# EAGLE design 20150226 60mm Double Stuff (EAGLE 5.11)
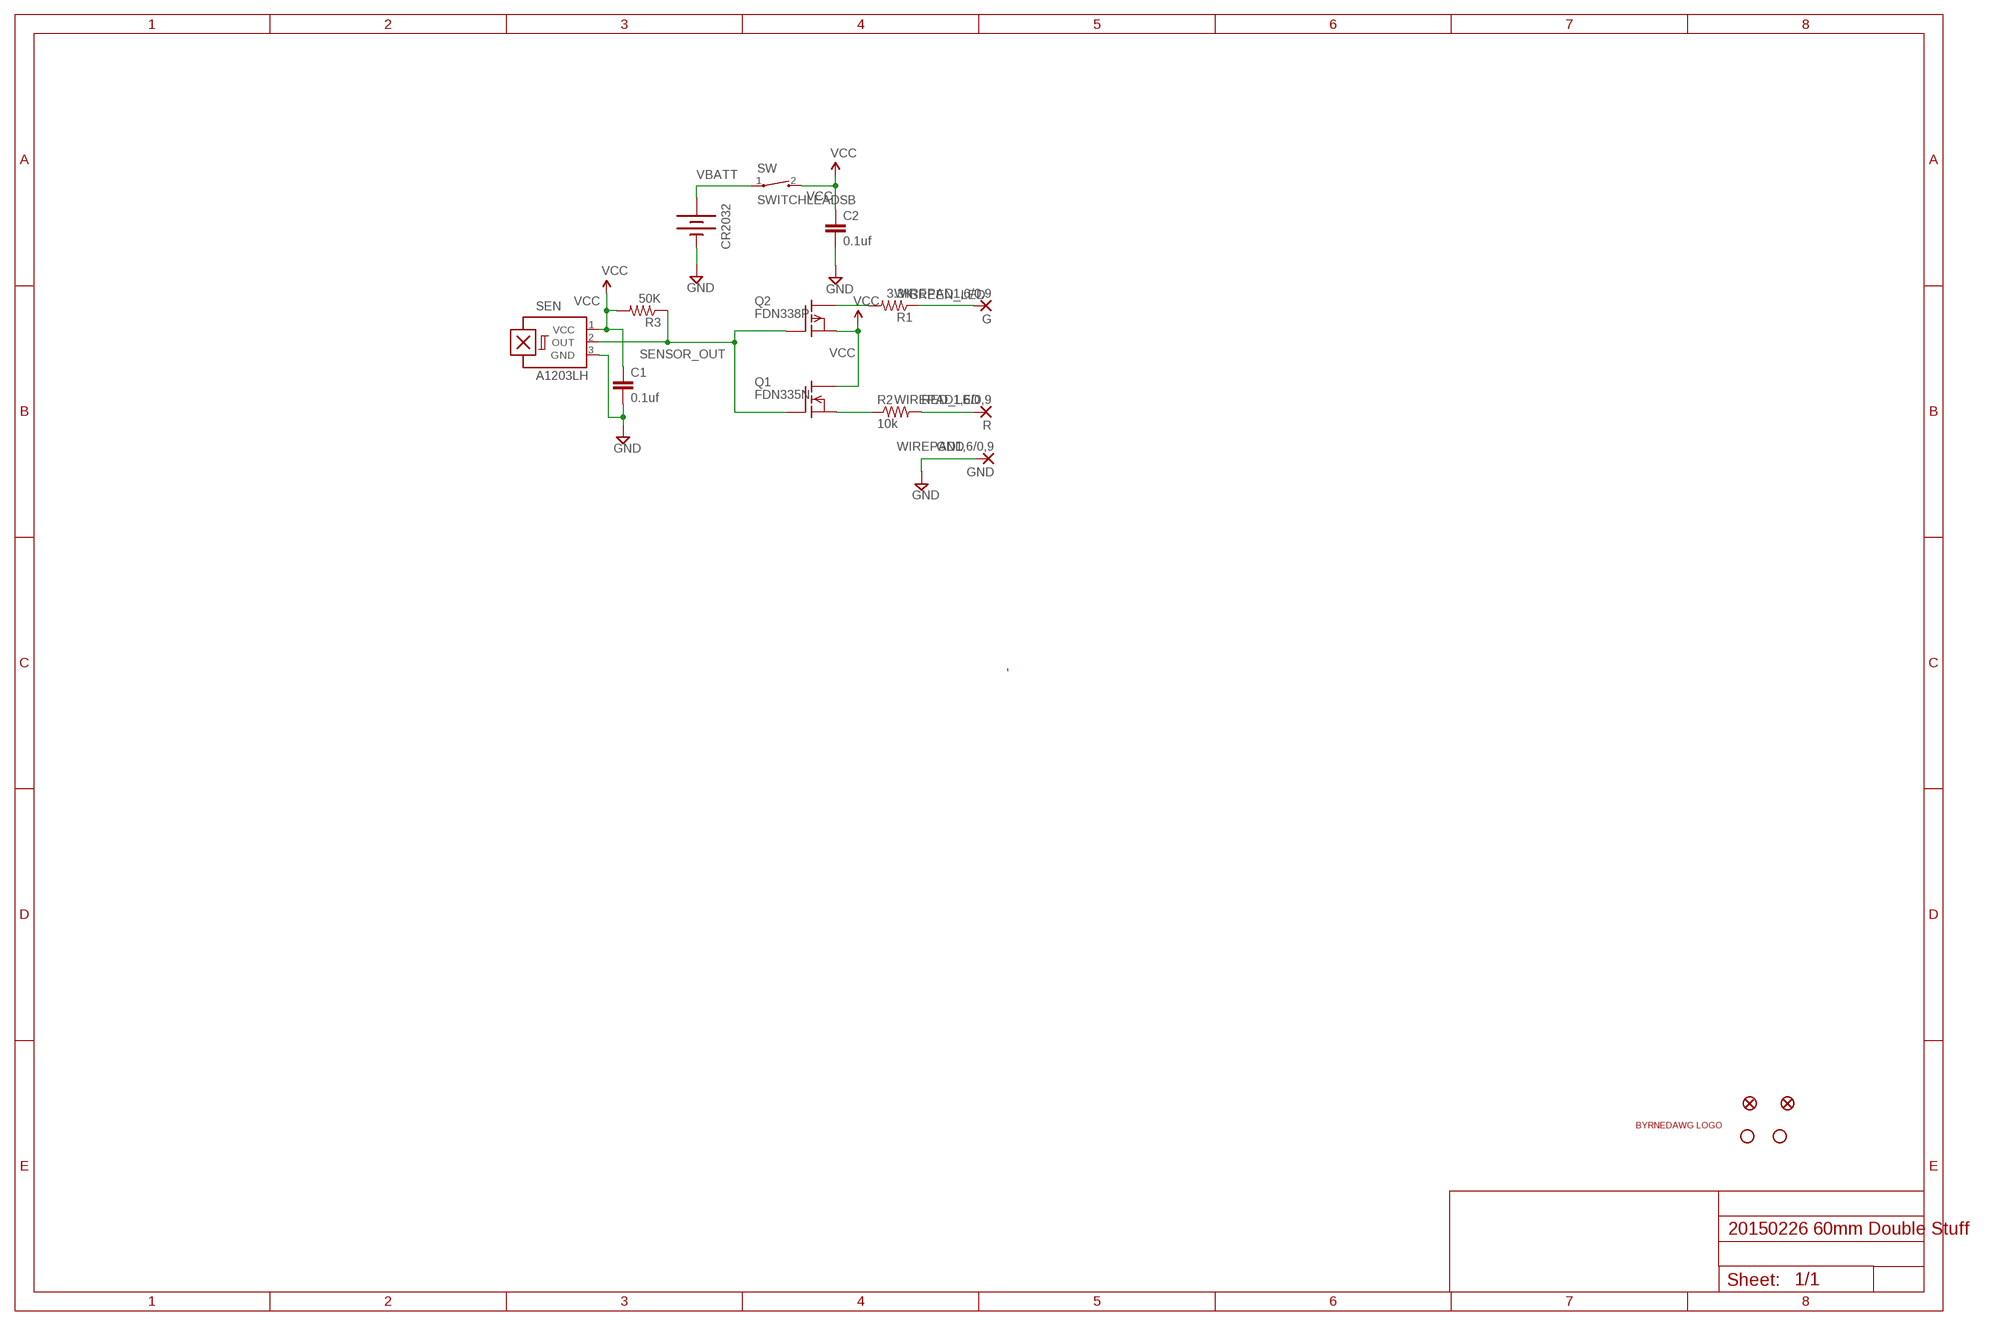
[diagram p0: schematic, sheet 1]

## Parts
C1  0.1uf  CAP0805  [0805]
C2  0.1uf  CAP0805  [0805]
CR2032  BATTERYFOB  [BATTERY_20MM_PTH_COMPACT]
G  WIREPAD1,6/0,9  [1,6/0,9]
GND  WIREPAD1,6/0,9  [1,6/0,9]
JP2  FIDUCIAL1X2  [FIDUCIAL-1X2]
JP3  FIDUCIAL1X2  [FIDUCIAL-1X2]
JP6  STAND-OFF  [STAND-OFF]
JP7  STAND-OFF  [STAND-OFF]
Q1  FDN335N  [SOT23]
Q2  FDN338P  [SOT23]
R  WIREPAD1,6/0,9  [1,6/0,9]
R1  3.3K  RESISTOR0805-RES  [0805]
R2  10k  RESISTOR0805-RES  [0805]
R3  50K  RESISTOR0805-RES  [0805]
SEN  A1203LH  [SOT23-W]
SW  SWITCHLEADSB  [1,6/0,8SWITCH]
U$2  BYRNEDAWGBIG_LABEL  [BYRNEDAWGBIGLABEL]

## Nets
GND: C1.2 C2.2 CR2032.2(-) GND.1(P) SEN.3(GND)
GREEN_LED: G.1(P) R1.1
N$1: Q1.2(S) R2.1
N$3: Q2.3(D) R1.2
RED_LED: R2.2 R.1(P)
SENSOR_OUT: Q1.1(G) Q2.1(G) R3.1 SEN.2(OUT)
VBATT: CR2032.1(+) SW.1
VCC: C1.1 C2.1 Q1.3(D) Q2.2(S) R3.2 SEN.1(VCC) SW.2

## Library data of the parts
C1 C2 = SparkFun:CAP: Capacitor
CR2032 = SparkFun:BATTERY: Battery Holders
G GND R = wirepad:WIREPAD: Wire PAD connect wire on PCB
JP2 JP3 = SparkFun:FIDUCIAL: Fiducial Alignment Points
JP6 JP7 = SparkFun:STAND-OFF: Stand Off
Q1 = fairchild-semic:FDN335N: N-Channel Enhancement MOSFET 2.5V
Q2 = fairchild-semic:FDN338P: P-Channel Enhancement MOSFET 2.5V
R1-R3 = SparkFun:RESISTOR: Resistor
SEN = allegro:A12*?: Hall-effect bipolar switch Source: http://www.allegromicro.com/en/Products/Part_Numbers/1202/1202.pdf; MF: ALLEGRO MICROSYSTEMS, INC.; MPN: A1203LLHLT-T; OC_FARNELL: 1791384; OC_NEWARK: 31K6608
SW = User_Created:SWITCHLEADS: CT10 Series Molded Switch
U$2 = logo:BYRNEDAWG

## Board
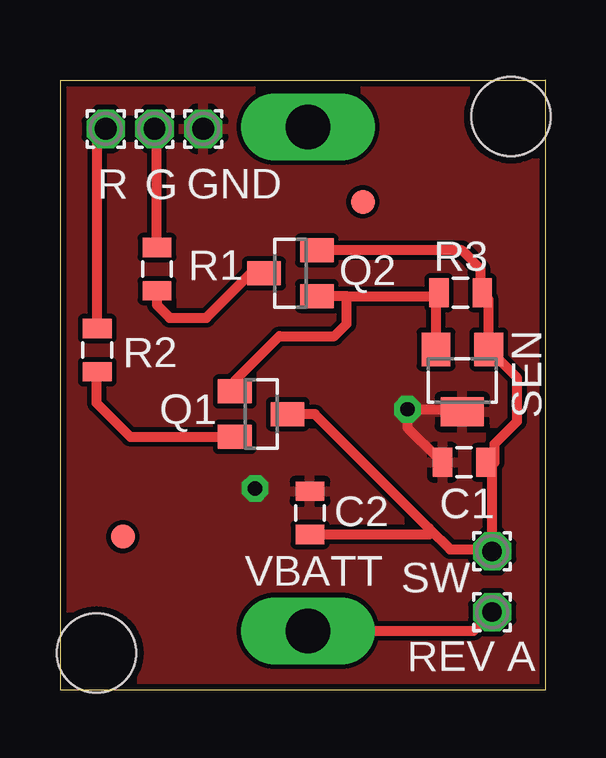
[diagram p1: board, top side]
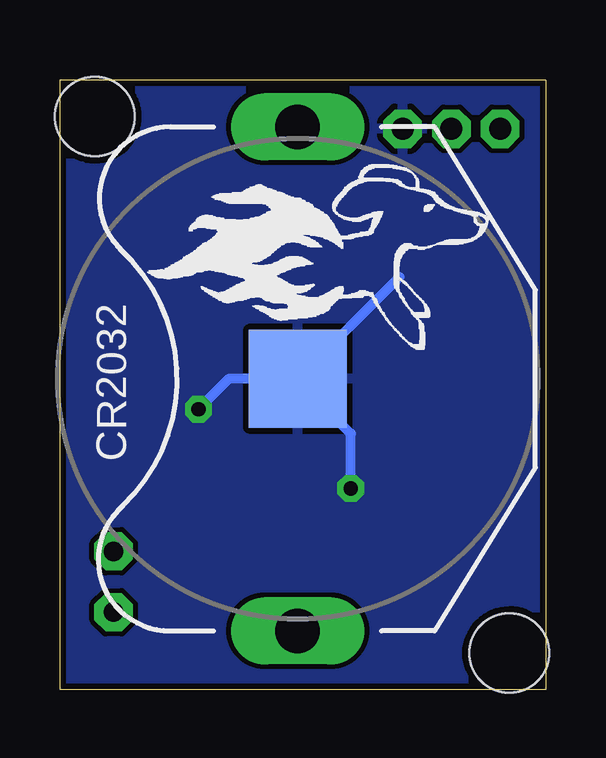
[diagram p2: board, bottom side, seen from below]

Size 20.24 x 25.41 mm. Coordinates in mm from the lower left corner, seen from the top.
Outline: 20.24,25.4 20.24,0 0,0 0,25.4 20.24,25.4
Outline: 20.24,25.4 20.24,25.41
Copper layers (1*16): Top 0.035mm / dielectric 1.5mm / Bottom 0.035mm
Design rules "SparkFun": minimum track width 8mil, minimum drill 20mil, track to track 8mil, track to pad 8mil, pad to pad 8mil, via to via 8mil, smd to smd 8mil, copper to edge 10mil, drill to drill 8mil, minimum pad ring 12mil, minimum via ring 10mil, stop-mask expansion 4mil, vias tented up to drill 25mil, thermal gap 10mil

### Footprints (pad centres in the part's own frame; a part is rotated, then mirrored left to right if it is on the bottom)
0805 = smd 0.8 x 1.2: 1 -0.9,0; 2 0.9,0
BATTERY_20MM_PTH_COMPACT = drill 1.854 long: 1 -10.5,0; 3 10.5,0 | smd 4.064 x 4.064: 2 0,0
1,6/0,9 = drill 0.914 pad 1.6 octagon: 1 0,0
FIDUCIAL-1X2 = smd 1 x 1: 1 0,0
STAND-OFF = hole 3.302: 0,0
SOT23 = smd 1 x 1.4: 1 -0.95,-1.1; 2 0.95,-1.1; 3 0,1.1
SOT23-W = smd 1.2 x 1.4: 1 -1.1,-1.3; 2 1.1,-1.3 | smd 1.8 x 1.2: 3 0,1.3
1,6/0,8SWITCH = drill 0.813 pad 1.6 octagon: 1 0,0; 2 2.54,0

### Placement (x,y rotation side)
C1  16.84,9.47 180 top
C2  10.41,7.37 90 top
CR2032  10.34,12.95 90 bottom
G  3.94,23.37 0 top
GND  5.97,23.37 0 top
JP2  2.62,6.38 90 top
JP3  12.62,20.32 90 top
JP6  1.52,1.52 0 top
JP7  18.8,23.88 0 top
Q1  8.38,11.48 270 top
Q2  9.6,17.35 90 top
R  1.91,23.37 0 top
R1  4.04,17.53 270 top
R2  1.55,14.15 90 top
R3  16.69,16.54 0 top
SEN  16.76,12.88 180 top
SW  18.01,3.23 90 top
U$2  4.57,17.53 0 bottom

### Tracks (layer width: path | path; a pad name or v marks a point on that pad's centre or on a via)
GND  (via drill 0.6)
  Top 0.406: 16.4,11.58 SEN.3 16.66,11.68 v14.48,11.68 14.48,10.92 15.73,9.67 15.75,9.67 C1.2 | v8.13,8.38 8.24,8.27
  Bottom 0.406: 6.1,17.2 CR2032.2 10.41,12.95 | 10.41,12.95 13.21,12.95 v14.48,11.68 | v8.13,8.38 8.13,10.67 10.41,12.95
  pour Bottom: 0,0 0,25.4 20.32,25.4 20.32,0
  pour Top: 0,0 0,25.4 20.32,25.4 20.32,0
GREEN_LED
  Top 0.406: R1.1 4.04,23.27 G.1
N$1
  Top 0.406: Q1.2 2.93,10.53 1.52,11.94 1.52,13.22 R2.1
N$3
  Top 0.406: R1.2 4.04,16.03 4.57,15.49 6.1,15.49 7.87,17.27 8.43,17.27 Q2.3
RED_LED
  Top 0.406: R2.2 1.55,23.01 R.1
SENSOR_OUT
  Top 0.406: Q1.1 7.28,12.87 9.14,14.73 11.43,14.73 11.94,15.24 11.94,16.4 | SEN.2 15.66,16.41 R3.1 15.65,16.4 11.94,16.4 | 11.94,16.4 Q2.1
VBATT
  Top 0.406: CR2032.1 17.24,2.45 SW.1
VCC
  Top 0.406: Q1.3 10.62,11.48 15.37,6.73 | 15.37,6.73 16.26,5.84 17.93,5.84 SW.2 18.01,9.21 C1.1 18.11,9.47 18.11,10.24 19.05,11.18 19.05,12.99 SEN.1 17.86,16.26 R3.2 17.53,16.6 17.53,17.53 16.75,18.3 Q2.2 | C2.1 15.37,6.47 15.37,6.73

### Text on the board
tNames: VBATT | REV A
